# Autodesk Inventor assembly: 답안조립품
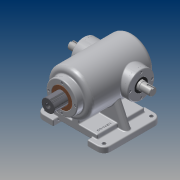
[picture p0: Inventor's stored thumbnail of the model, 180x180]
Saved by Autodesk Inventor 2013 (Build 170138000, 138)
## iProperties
Created: 2014-12
Part Number: 답안조립품
Document SubType Name: Assembly
Designer: HS001
Mass: 8641.3 g
Surface Area: 4328.77 cm^2
Volume: 2314.18 cm^3
Density: 3.73407 g/cm^3
Author: HS001
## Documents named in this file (13)
- C:\Users\HS001\Desktop\341228V1002\답안조립품.iam
- C:\Users\HS001\Desktop\341228V1002\본체.ipt
- C:\Users\HS001\Desktop\341228V1002\M4x0.7.ipt
- C:\Users\HS001\Desktop\341228V1002\베어링 6205.ipt
- 베어링 6205.ipt
- C:\Users\HS001\Desktop\341228V1002\부시.ipt
- C:\Users\HS001\Desktop\341228V1002\스프링-[가변].ipt
- C:\Users\HS001\Desktop\341228V1002\슬라이드 커버.ipt
- C:\Users\HS001\Desktop\341228V1002\슬라이드.ipt
- C:\Users\HS001\Desktop\341228V1002\오일실.ipt
- 오일실.ipt
- C:\Users\HS001\Desktop\341228V1002\축 커버.ipt
- C:\Users\HS001\Desktop\341228V1002\편심축.ipt
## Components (12 placed, 1 different names)
1. M4x0.7:2 — 각도:1
2. M4x0.7:3
3. M4x0.7:4
4. M4x0.7:5
5. M4x0.7:1 — 각도:2
6. M4x0.7:6
7. M4x0.7:7
8. M4x0.7:8
9. M4x0.7:9 — 각도:3
10. M4x0.7:10
11. M4x0.7:11
12. M4x0.7:12
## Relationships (3: Angle 3)
- 각도:1 [Angle]: M4x0.7:2
- 각도:2 [Angle]: M4x0.7:1
- 각도:3 [Angle]: M4x0.7:9
